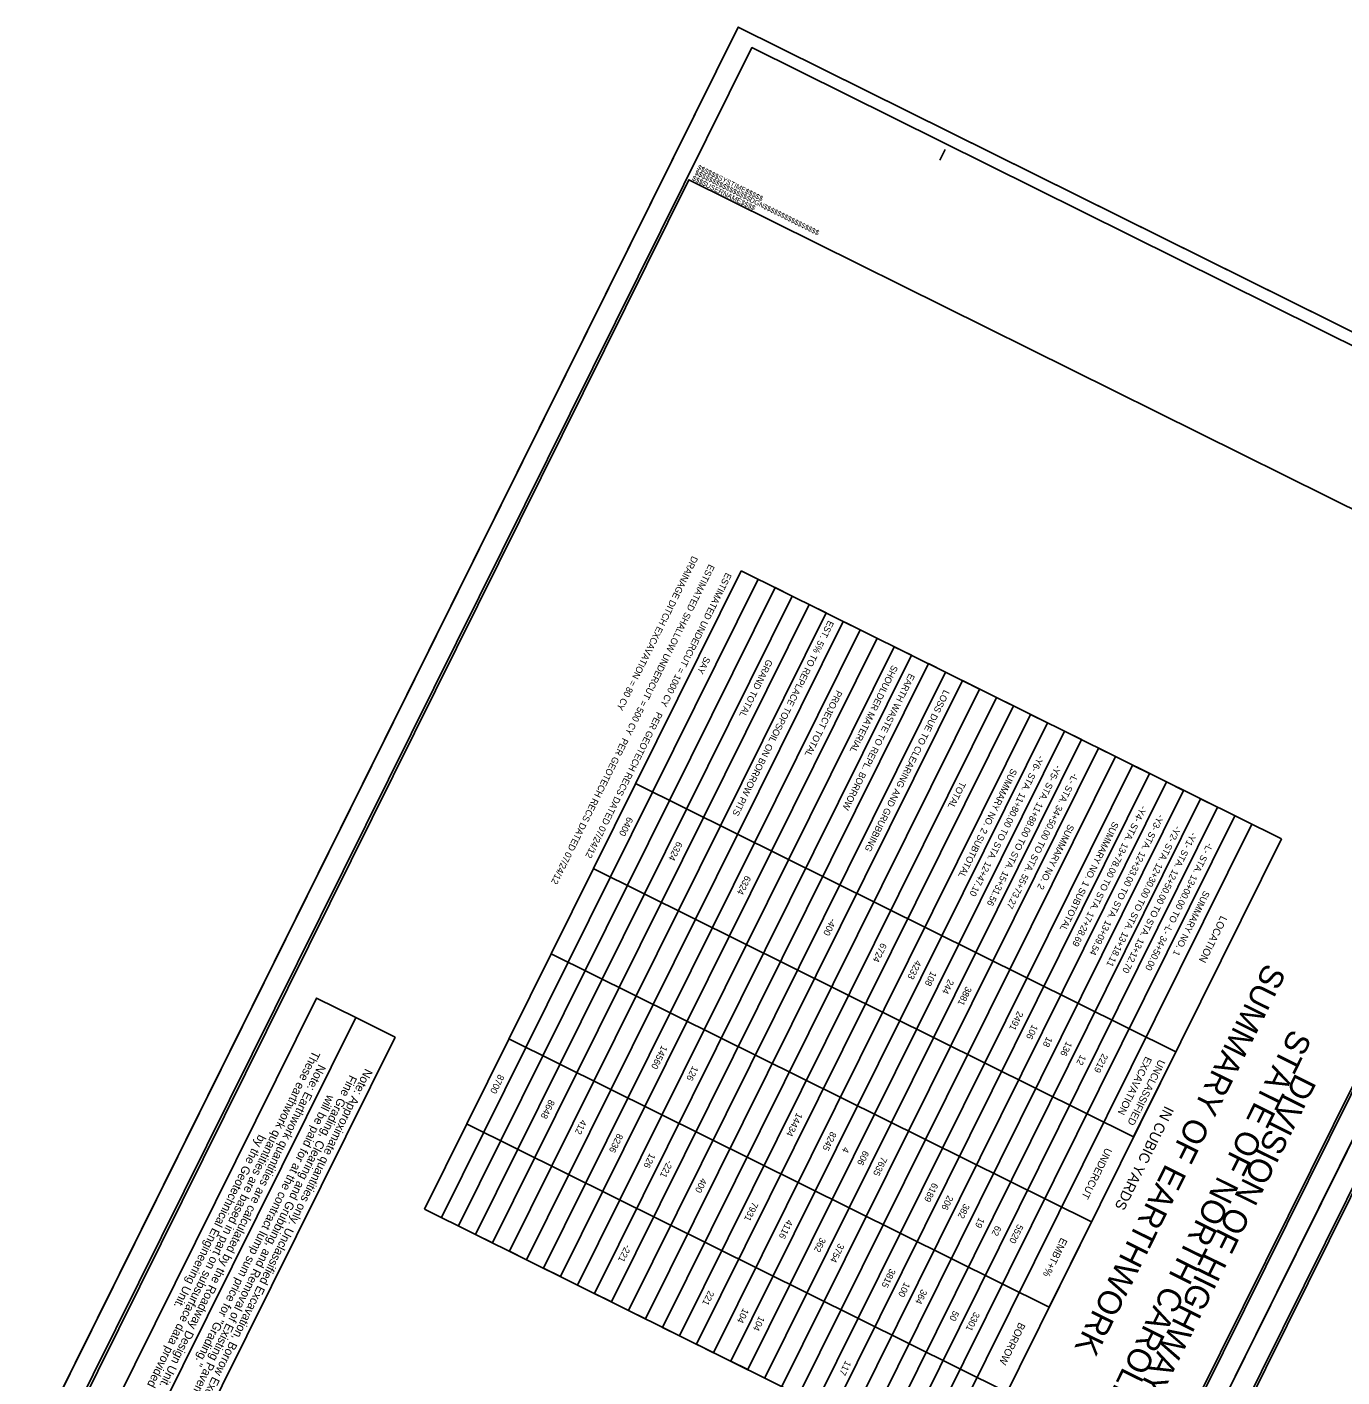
# Model space of a CAD drawing. Extents: x 2112338 to 2116552, y 435818 to 439065.
# Drawn here: x 2112338 to 2113722, y 437644 to 439065 of the extents above; entities that cross this region are included whole.
import ezdxf

# ---------------------------------------------------------------- set-up
doc = ezdxf.new("R2010")
doc.units = 0
for name, color, linetype in [('Old_Level_1', 7, 'Continuous'), ('Prop Grid Mask', 7, 'Continuous'), ('Prop XSC Text', 7, 'Continuous'), ('Sheet Cutting Line CELL', 7, 'Continuous'), ('Sheet Plot Border Inside CELL', 7, 'Continuous'), ('Sheet Plot Border Outside CELL', 7, 'Continuous'), ('Sheet Summary Earthwork CELL', 7, 'Continuous'), ('Sheet Summary Guardrail CELL', 7, 'Continuous')]:
    doc.layers.add(name, color=color, linetype=linetype)

msp = doc.modelspace()

# ---------------------------------------------------------------- linework, layer by layer
at = {"layer": 'Prop Grid Mask'}
for points in [[(2112684.3, 438022.2), (2112450.4, 437551), (2112409.1, 437571.5), (2112642.9, 438042.7)], [(2112725.6, 438001.6), (2112491.7, 437530.5), (2112450.4, 437551), (2112684.3, 438022.2)]]:
    msp.add_lwpolyline(points, close=True, dxfattribs=at)
at = {"layer": 'Sheet Cutting Line CELL'}
for p, q in [((2113086.9, 439064.7), (2112338.2, 437556.3)), ((2114072.2, 438575.7), (2113086.9, 439064.7)), ((2113323.5, 437067.3), (2114072.2, 438575.7)), ((2114072.2, 438575.7), (2113323.5, 437067.3))]:
    msp.add_line(p, q, dxfattribs=at)
at = {"layer": 'Sheet Plot Border Inside CELL'}
for points in [[(2113305.4, 437081.3), (2114046.3, 438574), (2113101.2, 439043.1), (2112360.3, 437550.3)], [(2114086.5, 438554.1), (2113345.6, 437061.3), (2114290.7, 436592.2), (2115031.6, 438085)]]:
    msp.add_lwpolyline(points, close=True, dxfattribs=at)
at = {"layer": 'Sheet Plot Border Outside CELL'}
for points in [[(2113323.5, 437067.3), (2114072.2, 438575.7), (2113086.9, 439064.7), (2112338.2, 437556.3)], [(2114072.2, 438575.7), (2113323.5, 437067.3), (2114308.8, 436578.2), (2115057.5, 438086.7)]]:
    msp.add_lwpolyline(points, close=True, dxfattribs=at)
at = {"layer": 'Sheet Summary Earthwork CELL'}
for p, q in [((2113304.8, 438935.9), (2113299.2, 438924.7)), ((2113035, 438904), (2113035, 438904)), ((2113035, 438904), (2113035, 438904)), ((2113035, 438904), (2113035, 438904)), ((2113035, 438904), (2113035, 438904)), ((2113035, 438904), (2113035, 438904)), ((2113035, 438904), (2113035, 438904)), ((2113035, 438904), (2113035, 438904)), ((2113035, 438904), (2113035, 438904)), ((2113035, 438904), (2113035, 438904)), ((2113089.9, 438492.5), (2112756.5, 437820.7)), ((2113089.9, 438492.5), (2112756.5, 437820.7)), ((2113089.9, 438492.5), (2113658.7, 438210.2)), ((2112774.4, 437811.8), (2113107.8, 438483.6)), ((2113125.8, 438474.7), (2112792.3, 437802.9)), ((2113143.7, 438465.8), (2113125.8, 438474.7)), ((2112810.2, 437794), (2113143.7, 438465.8)), ((2113161.6, 438456.9), (2112828.1, 437785.1)), ((2113179.5, 438448), (2113161.6, 438456.9)), ((2112846.1, 437776.2), (2113179.5, 438448)), ((2113197.4, 438439.1), (2112864, 437767.3)), ((2112881.9, 437758.4), (2113215.3, 438430.2)), ((2113215.3, 438430.2), (2113197.4, 438439.1)), ((2113233.2, 438421.4), (2112899.8, 437749.6)), ((2113251.2, 438412.5), (2112917.7, 437740.7)), ((2112935.6, 437731.8), (2113269.1, 438403.6)), ((2113269.1, 438403.6), (2113251.2, 438412.5)), ((2113287, 438394.7), (2112953.6, 437722.9)), ((2112971.5, 437714), (2113304.9, 438385.8)), ((2113304.9, 438385.8), (2113287, 438394.7)), ((2113322.8, 438376.9), (2112989.4, 437705.1)), ((2113340.7, 438368), (2113322.8, 438376.9)), ((2113007.3, 437696.2), (2113340.7, 438368)), ((2113358.6, 438359.1), (2113025.2, 437687.3)), ((2113376.6, 438350.2), (2113358.6, 438359.1)), ((2113043.1, 437678.4), (2113376.6, 438350.2)), ((2113394.5, 438341.3), (2113061, 437669.5)), ((2113079, 437660.6), (2113412.4, 438332.4)), ((2113412.4, 438332.4), (2113394.5, 438341.3)), ((2113430.3, 438323.6), (2113096.9, 437651.7)), ((2113114.8, 437642.9), (2113448.2, 438314.7)), ((2113448.2, 438314.7), (2113430.3, 438323.6)), ((2113466.1, 438305.8), (2113132.7, 437634)), ((2113484, 438296.9), (2113466.1, 438305.8)), ((2113150.6, 437625.1), (2113484, 438296.9)), ((2113502, 438288), (2113168.5, 437616.2)), ((2113519.9, 438279.1), (2113502, 438288)), ((2113186.4, 437607.3), (2113519.9, 438279.1)), ((2112978.8, 438268.6), (2113547.6, 437986.2)), ((2113537.8, 438270.2), (2113204.4, 437598.4)), ((2113222.3, 437589.5), (2113555.7, 438261.3)), ((2113555.7, 438261.3), (2113537.8, 438270.2)), ((2113573.6, 438252.4), (2113240.2, 437580.6)), ((2113258.1, 437571.7), (2113591.5, 438243.5)), ((2113591.5, 438243.5), (2113573.6, 438252.4)), ((2113609.5, 438234.6), (2113276, 437562.8)), ((2113293.9, 437553.9), (2113627.4, 438225.7)), ((2113658.7, 438210.2), (2113325.3, 437538.4)), ((2113503.1, 437896.7), (2112934.3, 438179)), ((2112889.9, 438089.4), (2113458.7, 437807.1)), ((2113414.2, 437717.5), (2112845.4, 437999.8)), ((2113547.6, 437986.2), (2113503.1, 437896.7)), ((2112800.9, 437910.3), (2113369.7, 437628)), ((2113325.3, 437538.4), (2112756.5, 437820.7)), ((2113458.7, 437807.1), (2113414.2, 437717.5)), ((2112828.1, 437785.1), (2112810.2, 437794)), ((2112864, 437767.3), (2112846.1, 437776.2)), ((2112899.8, 437749.6), (2112881.9, 437758.4)), ((2112953.6, 437722.9), (2112935.6, 437731.8)), ((2112989.4, 437705.1), (2112971.5, 437714)), ((2113025.2, 437687.3), (2113007.3, 437696.2)), ((2113061, 437669.5), (2113043.1, 437678.4)), ((2113096.9, 437651.7), (2113079, 437660.6))]:
    msp.add_line(p, q, dxfattribs=at)
msp.add_lwpolyline([(2113308.7, 437093.6), (2113975.5, 438437.2), (2113035, 438904), (2112368.1, 437560.4)], close=True, dxfattribs=at)
msp.add_lwpolyline([(2113018.3, 438870.4), (2113018.3, 438870.4)], dxfattribs=at)
at = {"layer": 'Sheet Summary Guardrail CELL'}
msp.add_lwpolyline([(2114294, 436604.6), (2114960.8, 437948.2), (2114020.3, 438415), (2113353.5, 437071.4)], close=True, dxfattribs=at)

# ---------------------------------------------------------------- texts
at = {"layer": 'Old_Level_1'}
for s, p in [('ESTIMATED SHALLOW UNDERCUT = 500 CY  PER GEOTECH RECS DATED 07/24/12', (2113056.1, 438499.9)), ('DRAINAGE DITCH EXCAVATION = 80 CY', (2113038.5, 438508.6)), ('ESTIMATED UNDERCUT = 1000 CY   PER GEOTECH RECS DATED 07/24/12', (2113074, 438491)), ('EST. 5% TO REPLACE TOPSOIL ON BORROW PITS', (2113181.7, 438440.7)), ('SAY', (2113051.6, 438402.7)), ('GRAND TOTAL', (2113117.2, 438399.8)), ('SHOULDER MATERIAL', (2113249, 438393.8)), ('EARTH WASTE TO REPL. BORROW', (2113266.9, 438384.9)), ('PROJECT TOTAL', (2113190.5, 438367.3)), ('LOSS DUE TO CLEARING AND GRUBBING', (2113303.4, 438367.6)), ('-Y6- STA. 11+80.00 TO STA. 12+47.10', (2113402.9, 438298.7)), ('-Y5- STA. 11+88.00 TO STA. 15+31.56', (2113421.2, 438288.6)), ('SUMMARY NO. 2 SUBTOTAL', (2113374.5, 438284.9)), ('-L- STA. 34+50.00 TO STA. 55+73.27', (2113439.1, 438280)), ('TOTAL', (2113320.5, 438271.2)), ('-Y4- STA. 13+78.00 TO STA. 17+28.69', (2113511, 438245.9)), ('6400', (2112970.4, 438234)), ('-Y3- STA. 12+33.00 TO STA. 13+09.54', (2113529.2, 438236.7)), ('SUMMARY NO. 2', (2113434.6, 438226.2)), ('SUMMARY NO. 1 SUBTOTAL', (2113481.5, 438229)), ('-Y2- STA. 12+30.00 TO STA. 13+18.11', (2113547.1, 438224.6)), ('-Y1- STA. 12+50.00 TO STA. 13+12.70', (2113563.7, 438217.9)), ('6324', (2113022.4, 438208)), ('-L- STA. 13+00.00 TO -L- 34+50.00', (2113580.9, 438206.7)), ('6324', (2113094.5, 438172.3)), ('SUMMARY NO. 1', (2113577.3, 438156.3)), ('-400', (2113184.4, 438127.3)), ('6724', (2113237.4, 438101.3)), ('4233', (2113274, 438083.2)), ('108', (2113289.9, 438071.5)), ('244', (2113308.1, 438063.1)), ('3881', (2113326.8, 438055.6)), ('2491', (2113381.1, 438029.5)), ('106', (2113396.5, 438015.4)), ('18', (2113411.8, 438002.6)), ('14560', (2113006.5, 437993.4)), ('136', (2113432.5, 437997.6)), ('12', (2113447.2, 437983.6)), ('2219', (2113470.3, 437984.9)), ('8700', (2112834.7, 437963)), ('126', (2113039, 437971.8)), ('8648', (2112887.9, 437936.5)), ('14434', (2113148.7, 437922.6)), ('412', (2112921.6, 437915.4)), ('8236', (2112959.8, 437900.8)), ('8245', (2113184.5, 437902.8)), ('126', (2112993.8, 437879.9)), ('4', (2113198.1, 437886.7)), ('606', (2113218.7, 437882.8)), ('7635', (2113237.8, 437876.3)), ('-221', (2113012.5, 437872.6)), ('400', (2113048.1, 437853.9)), ('6189', (2113291.5, 437848.9)), ('206', (2113307.4, 437835.7)), ('7931', (2113102.1, 437828.7)), ('382', (2113324.6, 437826.9)), ('4116', (2113138.6, 437810.2)), ('19', (2113340.5, 437812.2)), ('5520', (2113381.1, 437805.3)), ('362', (2113173.3, 437791.4)), ('62', (2113358, 437803.9)), ('-221', (2112968.4, 437783.8)), ('3754', (2113192.6, 437785.1)), ('3815', (2113246.7, 437758.6)), ('221', (2113055.7, 437735.4)), ('100', (2113261.9, 437744.2)), ('364', (2113279.9, 437736.8)), ('104', (2113092.2, 437716.8)), ('104', (2113109, 437708.5)), ('50', (2113313.5, 437714.3)), ('3301', (2113335.3, 437713)), ('117', (2113199.9, 437661.7))]:
    msp.add_text(s, height=7, rotation=243.6038, dxfattribs=at).set_placement(p)
at = {"layer": 'Prop XSC Text'}
for s, p in [('These earthwork quantities are based in part on subsurface data provided', (2112639.2, 437988)), ('Note: Earthwork quantities are calculated by the Roadway Design Unit.', (2112645.2, 437973.7)), (' Fine Grading, Clearing and Grubbing, and Removal of Existing Pavement', (2112679.5, 437965.5)), ('Note: Approximate quantities only. Unclassified Excavation, Borrow Excavation,', (2112694.4, 437969.1)), (' will be paid for at the contract lump sum price for "Grading."', (2112656, 437944.7)), (' by the Geotechnical Engineering Unit.', (2112583.7, 437902.8))]:
    msp.add_text(s, height=9, rotation=243.6038, dxfattribs=at).set_placement(p)
at = {"layer": 'Sheet Summary Earthwork CELL'}
for s, height, rotation, p in [('$$$$$$$$$$$$$$$$DGN$$$$$$$$$$$$$$$$', 5.25, 333.6038, (2113040.5, 438909.8)), ('$$$$$$SYSTIME$$$$$', 5.25, 333.6038, (2113043.2, 438915.2)), ('$$$$USERNAME$$$$', 5.25, 333.6038, (2113037.6, 438903.9)), ('LOCATION', 7.75, 243.6038, (2113595, 438129.9)), ('SUMMARY OF EARTHWORK', 25, 243.6038, (2113641.9, 438080.6)), ('STATE OF NORTH CAROLINA', 25, 243.6038, (2113668.9, 438011.3)), ('EXCAVATION', 7.75, 243.6038, (2113515.8, 437981.9)), ('UNCLASSIFIED', 7.75, 243.6038, (2113529.8, 437978.7)), ('DIVISION OF HIGHWAYS', 25, 243.6038, (2113673.7, 437964.8)), ('IN CUBIC YARDS', 11, 243.6038, (2113536, 437930.1)), ('UNDERCUT', 7.75, 243.6038, (2113473.8, 437885.7)), ('EMBT+%', 7.75, 243.6038, (2113426.8, 437791.1)), ('BORROW', 7.75, 243.6038, (2113382.6, 437702))]:
    msp.add_text(s, height=height, rotation=rotation, dxfattribs=at).set_placement(p)

doc.saveas('drawing.dxf')
